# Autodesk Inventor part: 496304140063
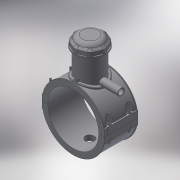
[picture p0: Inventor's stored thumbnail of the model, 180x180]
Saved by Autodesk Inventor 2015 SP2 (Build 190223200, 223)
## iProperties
Created: 2017-07
Part Number: 496304140063
Material: Generic
Description: PLASSON TAPPING SADDLE 140x63
Document SubType Name: Modeling
Designer: KIM
Mass: 1079.11 g
Surface Area: 2567.18 cm^2
Volume: 1079.11 cm^3
Density: 1 g/cm^3
Appearance: Default
Author: KIM
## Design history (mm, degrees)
derived "496304.ipt"
feature "Solid1::496304.ipt"
feature "Solid2::496304.ipt"
feature "Solid4::496304.ipt"
feature "Solid5::496304.ipt"
tag "TaggingFeature1"
body "Solid1"
body "Solid2"
other parameters: "d3" = 35, "d4" = 118, "d5" = 0, "d6" = 0.1, "d8" = 0, "d19" = 6, "d20" = 6, "d21" = 70.8, "d23" = 0, "d24" = 35.4, "d26" = 0, "d29" = 3, "d30" = 46.66667, "d31" = 6, "d32" = 0, "d33" = 0, "d34" = 0.6, "d40" = 82.992, "d41" = 74.2, "d43" = 0, "d45" = 0, "d47" = 150.6, "d70" = 15, "d72" = 0, "d73" = 6, "d75" = 5, "d76" = 0, "d77" = 7, "d79" = 15, "d80" = 47.2, "d82" = 5 deg, "d84" = 4, "d85" = 14, "d86" = 0, "d87" = 3, "d88" = 0, "d89" = 1, "d90" = 1, "d91" = 94.4, "d92" = 0, "d93" = 0.5, "d94" = 73.68421, "d96" = 162.792, "d97" = 2.36, "d98" = 0, "d102" = 1.4, "d120" = 140 deg, "d121" = 24.228, "d122" = 20 deg, "d123" = 319.2, "d124" = 95.76, "d126" = 0, "d143" = 144.2, "d145" = 15.07692, "d149" = 2.1, "d150" = 16.58462, "d153" = 118, "d154" = 0, "d156" = 79.8, "d157" = 160 deg, "d159" = 3.92, "d161" = 2.1, "d162" = 70.8, "d163" = 0, "d167" = 14, "d168" = 77.85366, "d170" = 3.375, "d172" = 0, "d173" = 1, "d176" = 20 deg, "d177" = 9.8, "d178" = 19.6, "d180" = 0, "d183" = 7.84, "d184" = 7.84, "d185" = 38.35, "d186" = 38.35, "d187" = 79.8, "d188" = 5.88, "d189" = 9.8, "d190" = 0, "d191" = 119.7, "d193" = 6.3, "d194" = 4.13, "d195" = 90 deg, "d197" = 0, "d199" = 0, "d200" = 9.8, "d202" = 0, "d203" = 177, "d204" = 70.49, "d205" = 51.94, "d206" = 63.07, "d207" = 132.75, "d208" = 138.06, "d209" = 164.61, "d210" = 63.812, "d211" = 74.2, "d212" = 59.36, "d213" = 29.25, "d216" = 0, "d217" = 14, "d218" = 14, "d219" = 2.8, "d224" = 0, "d230" = 5.6, "d233" = 6, "d237" = 35.4, "d238" = 6.02433, "d240" = 35.4, "d241" = 35.4, "d242" = 35.4, "d243" = 6, "d244" = 35.4, "d245" = 35.4, "d246" = 35.4, "d247" = 6, "d248" = 6, "d249" = 6, "d251" = 35.4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
